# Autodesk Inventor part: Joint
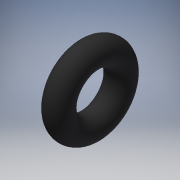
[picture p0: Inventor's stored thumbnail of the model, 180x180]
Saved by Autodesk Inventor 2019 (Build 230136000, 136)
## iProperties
Created: 2018-06
Part Number: Joint
Material: Caoutchouc
Document SubType Name: Modeling
Designer: Fabian Perrée
Density: 0.93 g/cm^3
Appearance: Caoutchouc - Noir
Author: Fabian Perrée
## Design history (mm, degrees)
sketch "Esquisse1"
  geometry: L1 (-2.1, 0)-(2.1, 0) reference; C1 r 1.5 at (0, 3.75); 1 further point
  constraints: 1 centre point, 1 vertical alignment
  dimensions: "d0" = 3 diameter of C1; "d1" = 3.75 distance of point (0, 0) C1.centre
revolve "Révolution1" sketch "Esquisse1" stored, may be unused: angle "d2" = 90 deg
node "Solide1"
